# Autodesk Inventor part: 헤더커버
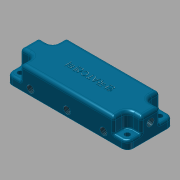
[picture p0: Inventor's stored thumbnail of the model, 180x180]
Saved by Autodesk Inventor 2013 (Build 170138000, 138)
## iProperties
Created: 2015-11
Part Number: 헤더커버
Material: 알루미늄 6061
Document SubType Name: Modeling
Designer: mduedu
Density: 2.71 g/cm^3
Mass: 171.77 g
Surface Area: 160.862 cm^2
Volume: 63.3837 cm^3
Author: mduedu
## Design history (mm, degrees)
sketch "스케치1"
  geometry: L1 (52.5, 20)-(-52.5, 20); L2 (-52.5, 20)-(-52.5, -20); L3 (-52.5, -20)-(52.5, -20); L4 (52.5, -20)-(52.5, 20); L5 (52.5, 20)-(-52.5, -20); L6 (-52.5, 20)-(52.5, -20); 1 further point
  constraints: 12 end point, 2 midpoint, 2 parallel, 1 horizontal, 1 perpendicular
  dimensions: "d0" = 105 distance of L3.end L2.end; "d1" = 40 distance of L2.end L1.end
extrude "돌출1" new body sketch "스케치1" distance "d2" = 20; taper "d3" = 0 deg
sketch "스케치2"
  geometry: L1 (-52.5, -20)-(-52.5, 20) reference; L2 (-52.5, 20)-(52.5, 20) reference; L3 (52.5, 20)-(52.5, -20) reference; L4 (52.5, -20)-(-52.5, -20) reference; L5 (-52.5, 20)-(-40.5, 20); L6 (-40.5, 20)-(-40.5, 8); L7 (-40.5, 8)-(-52.5, 8); L8 (-52.5, 8)-(-52.5, 20); L9 (52.5, 20)-(40.5, 20); L10 (40.5, 20)-(40.5, 8); L11 (40.5, 8)-(52.5, 8); L12 (52.5, 8)-(52.5, 20); L13 (52.5, -20)-(40.5, -20); L14 (40.5, -20)-(40.5, -8); L15 (40.5, -8)-(52.5, -8); L16 (52.5, -8)-(52.5, -20); L17 (-52.5, -20)-(-40.5, -20); L18 (-40.5, -20)-(-40.5, -8); L19 (-40.5, -8)-(-52.5, -8); L20 (-52.5, -8)-(-52.5, -20); 1 further point
  constraints: 32 end point, 8 parallel, 6 equal length, 4 horizontal, 4 perpendicular
  dimensions: "d4" = 12 distance of L6.end L7.end; "d5" = 12 distance of L5.end L6.end
extrude "돌출2" cut sketch "스케치2" distance "d6" = 13; taper "d7" = 0 deg
fillet "모깎기1" dims "d8" = 5
fillet "모깎기2" dims "d9" = 1
fillet "모깎기3" dims "d10" = 5
fillet "모깎기4" dims "d11" = 2
fillet "모깎기5" dims "d12" = 3
sketch "스케치3"
  geometry: L1 (-46.5, -14)-(46.5, -14); L2 (46.5, -14)-(46.5, 14); L3 (46.5, 14)-(-46.5, 14); L4 (-46.5, 14)-(-46.5, -14); L5 (-46.5, -14)-(46.5, 14); L6 (46.5, -14)-(-46.5, 14); L7 (47.5, 20)-(-47.5, 20) reference; L8 (52.5, -15)-(52.5, 15) reference; 5 further points
  constraints: 12 end point, 4 coincident, 2 midpoint, 2 parallel, 1 horizontal, 1 perpendicular
  dimensions: "d13" = 6 distance between parallel lines of L3 L7; "d14" = 6 distance between parallel lines of L2 L8
hole "구멍1" sketch "스케치3" at (-46.5, 14), (46.5, 14), (46.5, -14), (-46.5, -14) diameter "d15" = 4.5; stored, may be unused: countersink angle "d19" = 90 deg, drill point angle "d21" = 118 deg; dims "d16" = 6, "d17" = 4, "d18" = 2, "d20" = 8
sketch "스케치4"
  geometry: L1 (47.5, -20)-(-47.5, -20) reference; L2 (52.5, 15)-(52.5, -15) reference; L3 (-47.5, 20)-(47.5, 20) reference; L4 (-52.5, -15)-(-52.5, 15) reference; L5 (-52.5, 0)-(52.5, 0); C1 r 12.25 at (0, 0); C2 r 2.25 at (46.5, 14) reference; C3 r 2.25 at (-46.5, -14) reference; C4 r 2.25 at (46.5, -14) reference; C5 r 2.25 at (-46.5, 14) reference; C6 r 12.25 at (-32, 0); C7 r 12.25 at (32, 0); A1 r 5 centre (-47.5, -15) between (-52.5, -15) and (-47.5, -20) reference; A2 r 5 centre (47.5, -15) between (47.5, -20) and (52.5, -15) reference; A3 r 5 centre (47.5, 15) between (52.5, 15) and (47.5, 20) reference; A4 r 5 centre (-47.5, 15) between (-47.5, 20) and (-52.5, 15) reference; 1 further point
  constraints: 3 centre point, 2 end point, 2 midpoint, 2 point on line, 1 coincident
  dimensions: "d22" = 24.5 diameter of C1; "d23" = 24.5 diameter of C7 (= d22); "d24" = 24.5 diameter of C6 (= d22); "d25" = 32 distance of point (0, 0) C6.centre; "d26" = 32 distance of C7.centre point (0, 0) (= d25)
extrude "돌출3" cut sketch "스케치4" distance "d27" = 8; taper "d28" = 0 deg
fillet "모깎기6" dims "d29" = 5
sketch "스케치5"
  geometry: L1 (-52.5, 12)-(-47.119, 12); L2 (-40.191, 8)-(-37.635, 3.574); L3 (-52.5, 17)-(-52.5, 8) reference; L4 (-47.5, 0)-(-52.5, 0) reference; L5 (37.5, 20)-(-37.5, 20) reference; L6 (0, 0)-(0, 20); L7 (52.5, 12)-(47.119, 12); L8 (40.191, 8)-(37.635, 3.574); A1 r 8 centre (-47.119, 4) between (-40.191, 8) and (-47.119, 12); A2 r 8 centre (47.119, 4) between (47.119, 12) and (40.191, 8); 1 further point
  constraints: 10 end point, 5 symmetric about line, 4 point on circle, 3 point on line, 2 centre point, 2 tangent, 1 horizontal, 1 midpoint, 1 other
  dimensions: "d30" = 10 distance of L1.start point (-42.5, 12); "d32" = 120 deg angle of L2 L1; "d34" = 12 distance between parallel lines of L1 L4; "d35" = 8 radius of A1
sketch "스케치6"
  geometry: L1 (20, -5)-(20, 5) reference; L2 (8, -20)-(17, -20) reference; L3 (12, -20)-(12, -14.619); L4 (8, -7.691)-(3.81, -5.272); L5 (0, -20)-(0, -15) reference; A1 r 8 centre (4, -14.619) between (12, -14.619) and (8, -7.691); 2 further points
  constraints: 4 end point, 3 point on line, 2 point on circle, 2 tangent, 1 centre point, 1 perpendicular
  dimensions: "d36" = 10 distance of L3.start point (12, -10); "d38" = 12 distance between parallel lines of L3 L5; "d39" = 120 deg angle of L3 L4; "d40" = 8 radius of A1
node "작업점1"
node "작업점2"
node "작업점3"
hole "구멍2" diameter "d43" = 5.944; stored, may be unused: countersink angle "d49" = 90 deg, drill point angle "d51" = 0 deg; dims "d41" = 10, "d42" = 10, "d44" = 6.886, "d45" = 0.62479, "d46" = 5.959, "d47" = 4, "d48" = 2, "d50" = 6.9
hole "구멍3" diameter "d54" = 5.944; stored, may be unused: countersink angle "d60" = 90 deg, drill point angle "d62" = 0 deg; dims "d52" = 10, "d53" = 10, "d55" = 6.886, "d56" = 0.62479, "d57" = 5.959, "d58" = 4, "d59" = 2, "d61" = 6.9
hole "구멍4" diameter "d65" = 5.944; stored, may be unused: countersink angle "d71" = 90 deg, drill point angle "d73" = 0 deg; dims "d63" = 10, "d64" = 10, "d66" = 6.886, "d67" = 0.62479, "d68" = 5.959, "d69" = 4, "d70" = 2, "d72" = 6.9
sketch "스케치7"
  geometry: C1 r 2.972 at (15, 12) reference; 1 further point
sketch "스케치8"
  geometry: C1 r 2.972 at (15, 12) reference; 1 further point
sketch "스케치9"
  geometry: C1 r 2.972 at (47.5, 12) reference; 1 further point
feature "스윕1" dims "d74" = 0
feature "스윕2" dims "d75" = 0
feature "스윕3" dims "d76" = 0
sketch "스케치10"
  geometry: L1 (0, 0)-(95, 0) reference; L2 (22.75, 8)-(8.768, 8) reference; L3 (54.75, 8)-(40.25, 8) reference; L4 (86.232, 8)-(72.25, 8) reference; L5 (15.759, 8)-(15.759, 0); L6 (47.5, 8)-(47.5, 0); L7 (79.241, 8)-(79.241, 0); 5 further points
  constraints: 6 end point, 5 point on line, 3 midpoint, 2 horizontal alignment, 2 perpendicular, 1 parallel
  dimensions: "d77" = 5 distance from line of point (15.759, 5) L1
hole "구멍5" sketch "스케치10" at (15.759, 5), (47.5, 5), (79.241, 5) diameter "d78" = 5.944; stored, may be unused: countersink angle "d84" = 90 deg, drill point angle "d86" = 0 deg; dims "d79" = 6.886, "d80" = 0.62479, "d81" = 5.959, "d82" = 4, "d83" = 2, "d85" = 6.9
sketch "스케치11"
  geometry: C1 r 2.972 at (0, 0) reference; C2 r 2.972 at (31.741, 0) reference; C3 r 2.972 at (63.482, 0) reference; 1 further point
extrude "돌출4" cut sketch "스케치11" distance "d87" = 8; taper "d88" = 0 deg
sketch "스케치12"
  geometry: 2 further points
  constraints: 1 coincident, 1 other
feature "엠보싱1" sketch "스케치12" dims "d0" = 105, "d1" = 40, "d4" = 12, "d5" = 12, "d89" = 0.5, "d90" = 0
node "솔리드1"
node "투영된 루프1"
node "절단 모서리 투영1"
